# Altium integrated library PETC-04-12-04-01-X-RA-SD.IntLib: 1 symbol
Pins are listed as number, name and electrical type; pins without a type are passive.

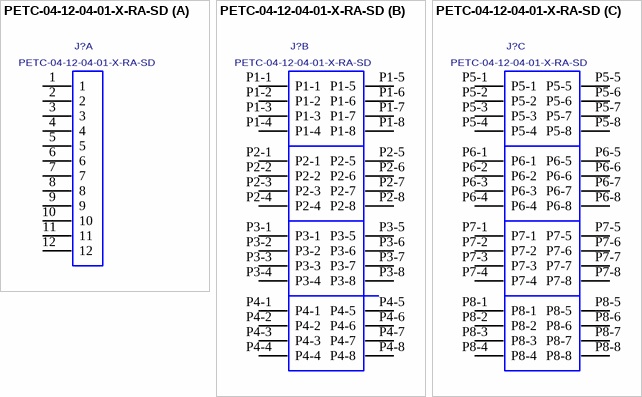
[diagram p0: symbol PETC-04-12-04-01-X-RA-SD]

## PETC-04-12-04-01-X-RA-SD
designator J?
RIGHT ANGLE POWER TERMINAL.; MANUFACTURER: SAMTEC
footprint PETC-04-12-04-01-X-RA-SD (Footprint not found)
part A pins: 1, 2, 3, 4, 5, 6, 7, 8, 9, 10, 11, 12
part B pins: P1-1, P1-2, P1-3, P1-4, P1-5, P1-6, P1-7, P1-8, P2-1, P2-2, P2-3, P2-4, P2-5, P2-6, P2-7, P2-8, P3-1, P3-2, P3-3, P3-4, P3-5, P3-6, P3-7, P3-8, P4-1, P4-2, P4-3, P4-4, P4-5, P4-6, P4-7, P4-8
part C pins: P5-1, P5-2, P5-3, P5-4, P5-5, P5-6, P5-7, P5-8, P6-1, P6-2, P6-3, P6-4, P6-5, P6-6, P6-7, P6-8, P7-1, P7-2, P7-3, P7-4, P7-5, P7-6, P7-7, P7-8, P8-1, P8-2, P8-3, P8-4, P8-5, P8-6, P8-7, P8-8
